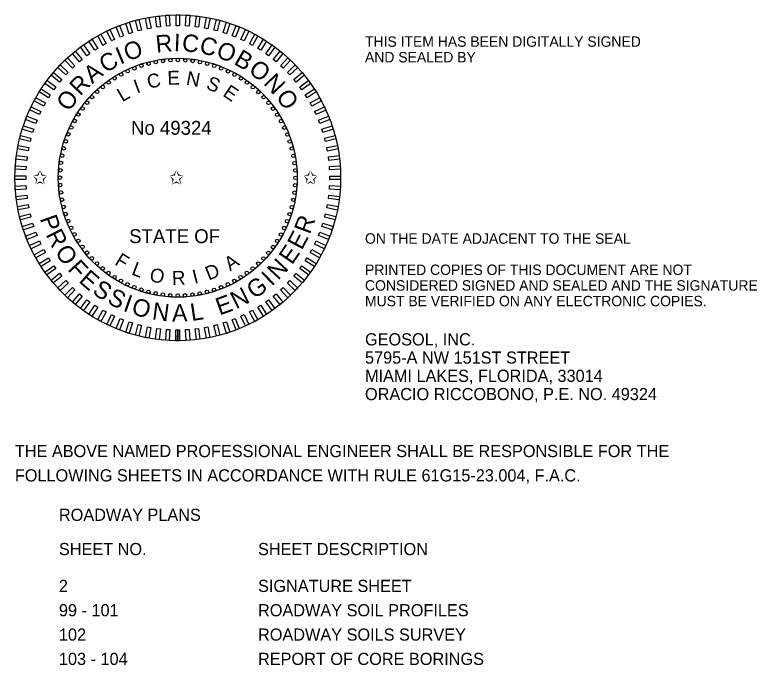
# Model space of a CAD drawing. Extents: x -811 to 10319, y -2309 to 9962.
# Drawn here: x -794.327 to -790.055, y -2192.952 to -2189.209 of the extents above; entities that cross this region are included whole.
import ezdxf

# ---------------------------------------------------------------- set-up
doc = ezdxf.new("R2010")
doc.units = 0
for name, color, linetype in [('PlotBorder_dp', 7, 'Continuous'), ('TextMinor', 7, 'Continuous'), ('TextMisc', 7, 'Continuous'), ('TextShtNo', 7, 'Continuous')]:
    doc.layers.add(name, color=color, linetype=linetype)

msp = doc.modelspace()

# ---------------------------------------------------------------- linework, layer by layer
at = {"layer": 'TextMinor'}
for radius in [0.9375, 0.6875]:
    msp.add_circle((-793.3899, -2190.1468), radius, dxfattribs=at)
at = {"layer": 'TextShtNo'}
for p, q in [((-793.3999, -2191.0843), (-793.4001, -2191.0218)), ((-793.3899, -2191.0843), (-793.3901, -2191.0218)), ((-793.3799, -2191.0843), (-793.3801, -2191.0218))]:
    msp.add_line(p, q, dxfattribs=at)
for points in [[(-793.5976, -2189.2967), (-793.6172, -2189.3018), (-793.6327, -2189.2413), (-793.6132, -2189.2363)], [(-793.5438, -2189.2854), (-793.5637, -2189.2892), (-793.5754, -2189.2278), (-793.5555, -2189.224)], [(-793.4895, -2189.2774), (-793.5095, -2189.2799), (-793.5173, -2189.218), (-793.4973, -2189.2155)], [(-793.4347, -2189.2729), (-793.4548, -2189.2741), (-793.4587, -2189.2118), (-793.4386, -2189.2106)], [(-793.3797, -2189.2718), (-793.3999, -2189.2718), (-793.3999, -2189.2093), (-793.3797, -2189.2093)], [(-793.3248, -2189.2741), (-793.3449, -2189.2729), (-793.341, -2189.2106), (-793.3209, -2189.2118)], [(-793.2701, -2189.28), (-793.2901, -2189.2774), (-793.2823, -2189.2155), (-793.2623, -2189.218)], [(-793.2159, -2189.2892), (-793.2357, -2189.2854), (-793.224, -2189.2241), (-793.2042, -2189.2279)], [(-793.1624, -2189.3018), (-793.182, -2189.2968), (-793.1664, -2189.2363), (-793.1469, -2189.2413)], [(-793.7025, -2189.3295), (-793.7213, -2189.3369), (-793.7443, -2189.2789), (-793.7255, -2189.2714)], [(-793.6506, -2189.3115), (-793.6698, -2189.3177), (-793.6891, -2189.2583), (-793.6699, -2189.2521)], [(-793.1098, -2189.3178), (-793.129, -2189.3115), (-793.1097, -2189.2521), (-793.0905, -2189.2584)], [(-793.0583, -2189.337), (-793.0771, -2189.3295), (-793.0541, -2189.2715), (-793.0353, -2189.2789)], [(-793.8025, -2189.3751), (-793.8202, -2189.3848), (-793.8503, -2189.3301), (-793.8326, -2189.3204)], [(-793.7532, -2189.3507), (-793.7715, -2189.3593), (-793.7981, -2189.3028), (-793.7798, -2189.2942)], [(-793.0081, -2189.3594), (-793.0264, -2189.3508), (-792.9998, -2189.2943), (-792.9815, -2189.3029)], [(-792.9594, -2189.3849), (-792.9771, -2189.3752), (-792.947, -2189.3205), (-792.9293, -2189.3302)], [(-793.8502, -2189.4025), (-793.8672, -2189.4134), (-793.9007, -2189.3606), (-793.8836, -2189.3498)], [(-792.9124, -2189.4135), (-792.9295, -2189.4026), (-792.896, -2189.3499), (-792.879, -2189.3607)], [(-793.896, -2189.4329), (-793.9123, -2189.4448), (-793.949, -2189.3943), (-793.9327, -2189.3824)], [(-792.8673, -2189.4449), (-792.8836, -2189.433), (-792.8469, -2189.3825), (-792.8306, -2189.3944)], [(-793.9815, -2189.502), (-793.9962, -2189.5158), (-794.0389, -2189.4703), (-794.0242, -2189.4565)], [(-793.9398, -2189.4661), (-793.9554, -2189.479), (-793.9952, -2189.4309), (-793.9796, -2189.418)], [(-792.8243, -2189.4791), (-792.8398, -2189.4662), (-792.8, -2189.4181), (-792.7845, -2189.431)], [(-792.7835, -2189.5159), (-792.7982, -2189.5021), (-792.7554, -2189.4566), (-792.7407, -2189.4704)], [(-794.0208, -2189.5404), (-794.0346, -2189.5551), (-794.0801, -2189.5124), (-794.0663, -2189.4976)], [(-792.745, -2189.5552), (-792.7589, -2189.5405), (-792.7133, -2189.4978), (-792.6995, -2189.5125)], [(-794.0576, -2189.5812), (-794.0705, -2189.5968), (-794.1186, -2189.5569), (-794.1057, -2189.5414)], [(-792.7092, -2189.5969), (-792.722, -2189.5813), (-792.6739, -2189.5415), (-792.6611, -2189.5571)], [(-794.0918, -2189.6242), (-794.1037, -2189.6406), (-794.1542, -2189.6039), (-794.1423, -2189.5875)], [(-792.676, -2189.6407), (-792.6878, -2189.6244), (-792.6373, -2189.5877), (-792.6255, -2189.604)], [(-794.1232, -2189.6693), (-794.1341, -2189.6864), (-794.1868, -2189.6529), (-794.176, -2189.6359)], [(-792.6456, -2189.6865), (-792.6564, -2189.6695), (-792.6037, -2189.636), (-792.5929, -2189.6531)], [(-794.1518, -2189.7163), (-794.1615, -2189.734), (-794.2162, -2189.7039), (-794.2065, -2189.6863)], [(-792.6182, -2189.7342), (-792.6279, -2189.7165), (-792.5732, -2189.6864), (-792.5635, -2189.7041)], [(-794.1773, -2189.765), (-794.1859, -2189.7833), (-794.2424, -2189.7567), (-794.2338, -2189.7384)], [(-792.5938, -2189.7835), (-792.6024, -2189.7652), (-792.5459, -2189.7386), (-792.5373, -2189.7569)], [(-794.1997, -2189.8152), (-794.2071, -2189.834), (-794.2652, -2189.811), (-794.2578, -2189.7922)], [(-792.5726, -2189.8342), (-792.58, -2189.8154), (-792.5219, -2189.7924), (-792.5145, -2189.8112)], [(-794.2189, -2189.8667), (-794.2252, -2189.8859), (-794.2846, -2189.8666), (-794.2783, -2189.8474)], [(-792.5545, -2189.8861), (-792.5608, -2189.8669), (-792.5014, -2189.8476), (-792.4952, -2189.8668)], [(-794.2349, -2189.9193), (-794.2399, -2189.9389), (-794.3004, -2189.9234), (-794.2954, -2189.9038)], [(-792.5398, -2189.9391), (-792.5448, -2189.9195), (-792.4844, -2189.904), (-792.4793, -2189.9235)], [(-794.2475, -2189.9728), (-794.2513, -2189.9927), (-794.3126, -2189.981), (-794.3088, -2189.9611)], [(-792.5284, -2189.9929), (-792.5322, -2189.973), (-792.4709, -2189.9613), (-792.4671, -2189.9812)], [(-794.2567, -2190.027), (-794.2593, -2190.0471), (-794.3212, -2190.0392), (-794.3187, -2190.0192)], [(-792.5205, -2190.0472), (-792.523, -2190.0272), (-792.4611, -2190.0194), (-792.4585, -2190.0394)], [(-794.2626, -2190.0817), (-794.2638, -2190.1018), (-794.3261, -2190.0979), (-794.3249, -2190.0778)], [(-792.5159, -2190.102), (-792.5172, -2190.0819), (-792.4549, -2190.078), (-792.4536, -2190.0981)], [(-794.2649, -2190.1366), (-794.2649, -2190.1568), (-794.3274, -2190.1568), (-794.3274, -2190.1366)], [(-792.5149, -2190.157), (-792.5149, -2190.1368), (-792.4524, -2190.1368), (-792.4524, -2190.157)], [(-794.2638, -2190.1916), (-794.2626, -2190.2117), (-794.3249, -2190.2157), (-794.3261, -2190.1955)], [(-792.5172, -2190.2119), (-792.516, -2190.1918), (-792.4536, -2190.1957), (-792.4549, -2190.2158)], [(-794.2593, -2190.2464), (-794.2568, -2190.2664), (-794.3187, -2190.2742), (-794.3212, -2190.2542)], [(-792.523, -2190.2666), (-792.5205, -2190.2466), (-792.4586, -2190.2544), (-792.4611, -2190.2744)], [(-794.2513, -2190.3008), (-794.2475, -2190.3206), (-794.3089, -2190.3323), (-794.3127, -2190.3125)], [(-792.5323, -2190.3208), (-792.5285, -2190.301), (-792.4671, -2190.3127), (-792.4709, -2190.3325)], [(-794.24, -2190.3546), (-794.2349, -2190.3741), (-794.2954, -2190.3896), (-794.3004, -2190.3701)], [(-792.5449, -2190.3743), (-792.5399, -2190.3547), (-792.4794, -2190.3703), (-792.4844, -2190.3898)], [(-794.2252, -2190.4075), (-794.219, -2190.4267), (-794.2784, -2190.446), (-794.2846, -2190.4268)], [(-792.5608, -2190.4269), (-792.5546, -2190.4077), (-792.4952, -2190.427), (-792.5014, -2190.4462)], [(-794.2072, -2190.4595), (-794.1998, -2190.4782), (-794.2578, -2190.5012), (-794.2653, -2190.4824)], [(-792.5801, -2190.4784), (-792.5726, -2190.4596), (-792.5146, -2190.4826), (-792.522, -2190.5014)], [(-794.186, -2190.5102), (-794.1774, -2190.5284), (-794.2339, -2190.555), (-794.2425, -2190.5367)], [(-792.6025, -2190.5286), (-792.5939, -2190.5103), (-792.5374, -2190.5369), (-792.546, -2190.5552)], [(-794.1616, -2190.5594), (-794.1519, -2190.5771), (-794.2066, -2190.6072), (-794.2163, -2190.5895)], [(-792.628, -2190.5773), (-792.6183, -2190.5596), (-792.5636, -2190.5897), (-792.5733, -2190.6074)], [(-794.1342, -2190.6071), (-794.1233, -2190.6241), (-794.1761, -2190.6576), (-794.1869, -2190.6405)], [(-792.6565, -2190.6243), (-792.6457, -2190.6072), (-792.593, -2190.6407), (-792.6038, -2190.6577)], [(-794.1038, -2190.6529), (-794.0919, -2190.6692), (-794.1424, -2190.7059), (-794.1543, -2190.6896)], [(-792.688, -2190.6694), (-792.6761, -2190.653), (-792.6256, -2190.6898), (-792.6374, -2190.7061)], [(-794.0706, -2190.6967), (-794.0577, -2190.7123), (-794.1058, -2190.7521), (-794.1187, -2190.7365)], [(-794.0347, -2190.7384), (-794.0209, -2190.7531), (-794.0664, -2190.7958), (-794.0802, -2190.7811)], [(-792.759, -2190.7532), (-792.7452, -2190.7385), (-792.6997, -2190.7813), (-792.7135, -2190.796)], [(-792.7222, -2190.7124), (-792.7093, -2190.6969), (-792.6612, -2190.7367), (-792.674, -2190.7522)], [(-793.9963, -2190.7777), (-793.9816, -2190.7915), (-794.0243, -2190.837), (-794.0391, -2190.8232)], [(-792.7983, -2190.7917), (-792.7836, -2190.7778), (-792.7409, -2190.8234), (-792.7556, -2190.8372)], [(-793.9555, -2190.8145), (-793.9399, -2190.8274), (-793.9797, -2190.8755), (-793.9953, -2190.8627)], [(-792.84, -2190.8275), (-792.8244, -2190.8147), (-792.7846, -2190.8628), (-792.8002, -2190.8756)], [(-793.9125, -2190.8487), (-793.8961, -2190.8606), (-793.9328, -2190.9111), (-793.9492, -2190.8993)], [(-792.8838, -2190.8607), (-792.8675, -2190.8488), (-792.8308, -2190.8994), (-792.8471, -2190.9112)], [(-793.8674, -2190.8802), (-793.8503, -2190.891), (-793.8838, -2190.9437), (-793.9008, -2190.9329)], [(-793.8204, -2190.9087), (-793.8027, -2190.9184), (-793.8328, -2190.9731), (-793.8504, -2190.9634)], [(-792.9773, -2190.9185), (-792.9596, -2190.9088), (-792.9295, -2190.9635), (-792.9472, -2190.9732)], [(-792.9296, -2190.8911), (-792.9126, -2190.8803), (-792.8791, -2190.933), (-792.8962, -2190.9438)], [(-793.7717, -2190.9342), (-793.7534, -2190.9428), (-793.78, -2190.9993), (-793.7983, -2190.9907)], [(-793.0265, -2190.9429), (-793.0083, -2190.9343), (-792.9817, -2190.9908), (-792.9999, -2190.9994)], [(-793.7215, -2190.9566), (-793.7027, -2190.9641), (-793.7257, -2191.0221), (-793.7445, -2191.0147)], [(-793.67, -2190.9759), (-793.6508, -2190.9821), (-793.6701, -2191.0415), (-793.6893, -2191.0352)], [(-793.6174, -2190.9918), (-793.5978, -2190.9968), (-793.6133, -2191.0573), (-793.6329, -2191.0523)], [(-793.1821, -2190.9969), (-793.1626, -2190.9919), (-793.1471, -2191.0523), (-793.1666, -2191.0574)], [(-793.1292, -2190.9822), (-793.11, -2190.9759), (-793.0907, -2191.0353), (-793.1099, -2191.0415)], [(-793.0772, -2190.9641), (-793.0585, -2190.9567), (-793.0355, -2191.0148), (-793.0543, -2191.0222)], [(-793.5639, -2191.0044), (-793.544, -2191.0082), (-793.5557, -2191.0695), (-793.5756, -2191.0658)], [(-793.5097, -2191.0137), (-793.4896, -2191.0162), (-793.4975, -2191.0781), (-793.5175, -2191.0756)], [(-793.455, -2191.0195), (-793.4348, -2191.0207), (-793.4388, -2191.0831), (-793.4589, -2191.0818)], [(-793.4001, -2191.0218), (-793.3799, -2191.0218), (-793.3799, -2191.0843), (-793.4001, -2191.0843)], [(-793.3451, -2191.0208), (-793.325, -2191.0195), (-793.321, -2191.0818), (-793.3412, -2191.0831)], [(-793.2903, -2191.0162), (-793.2703, -2191.0137), (-793.2625, -2191.0756), (-793.2825, -2191.0782)], [(-793.2359, -2191.0082), (-793.2161, -2191.0045), (-793.2044, -2191.0658), (-793.2242, -2191.0696)]]:
    msp.add_lwpolyline(points, close=True, dxfattribs=at)
for centre in [(-793.5987, -2189.5023), (-793.5578, -2189.4905), (-793.5163, -2189.4812), (-793.4742, -2189.4746), (-793.4319, -2189.4706), (-793.3893, -2189.4693), (-793.3468, -2189.4707), (-793.3044, -2189.4748), (-793.2624, -2189.4814), (-793.2209, -2189.4908), (-793.18, -2189.5027), (-793.7158, -2189.5529), (-793.6778, -2189.5336), (-793.6388, -2189.5167), (-793.14, -2189.5171), (-793.1009, -2189.5341), (-793.7524, -2189.5745), (-793.063, -2189.5534), (-793.0264, -2189.5751), (-793.8213, -2189.6245), (-793.7876, -2189.5984), (-792.9912, -2189.5991), (-792.9576, -2189.6252), (-793.8532, -2189.6526), (-792.9257, -2189.6533), (-793.9115, -2189.7145), (-793.8834, -2189.6826), (-792.8956, -2189.6835), (-792.8675, -2189.7154), (-793.9376, -2189.7481), (-792.8415, -2189.7491), (-793.9616, -2189.7833), (-792.8176, -2189.7843), (-793.9833, -2189.8199), (-792.7959, -2189.8209), (-794.0026, -2189.8578), (-792.7767, -2189.8589), (-794.034, -2189.9369), (-794.0196, -2189.8969), (-792.7598, -2189.8979), (-794.0459, -2189.9778), (-792.7454, -2189.938), (-792.7336, -2189.9789), (-794.0552, -2190.0193), (-792.7243, -2190.0204), (-794.0619, -2190.0613), (-792.7177, -2190.0625), (-794.066, -2190.1037), (-792.7137, -2190.1048), (-794.0674, -2190.1462), (-792.7124, -2190.1474), (-794.0661, -2190.1888), (-792.7138, -2190.1899), (-794.0621, -2190.2312), (-792.7178, -2190.2323), (-794.0555, -2190.2732), (-792.7245, -2190.2743), (-794.0462, -2190.3147), (-792.7338, -2190.3158), (-794.0344, -2190.3556), (-792.7457, -2190.3567), (-794.02, -2190.3957), (-792.7602, -2190.3967), (-794.0031, -2190.4348), (-792.7771, -2190.4358), (-793.9838, -2190.4727), (-792.7965, -2190.4737), (-793.9622, -2190.5093), (-792.8182, -2190.5103), (-793.9383, -2190.5446), (-793.9122, -2190.5782), (-792.8421, -2190.5455), (-793.8841, -2190.6102), (-792.8964, -2190.611), (-792.8682, -2190.5791), (-793.8541, -2190.6403), (-792.9265, -2190.641), (-793.8222, -2190.6684), (-793.7885, -2190.6946), (-792.9921, -2190.6952), (-792.9585, -2190.6692), (-793.7534, -2190.7185), (-793.7168, -2190.7402), (-793.064, -2190.7408), (-793.0274, -2190.7191), (-793.6788, -2190.7596), (-793.6398, -2190.7765), (-793.5998, -2190.7909), (-793.1811, -2190.7913), (-793.141, -2190.7769), (-793.1019, -2190.76), (-793.5589, -2190.8029), (-793.5174, -2190.8122), (-793.4754, -2190.8189), (-793.433, -2190.8229), (-793.3899, -2190.8243), (-793.3479, -2190.823), (-793.3055, -2190.819), (-793.2635, -2190.8124), (-793.222, -2190.8031)]:
    msp.add_circle(centre, 0.01, dxfattribs=at)

# ---------------------------------------------------------------- texts
at = {"layer": 'PlotBorder_dp'}
for s, height, p in [('THIS ITEM HAS BEEN DIGITALLY SIGNED ', 0.06, (-792.3122, -2189.393)), ('AND SEALED BY', 0.06, (-792.3122, -2189.483)), ('ON THE DATE ADJACENT TO THE SEAL', 0.06, (-792.3122, -2190.5264)), ('PRINTED COPIES OF THIS DOCUMENT ARE NOT ', 0.06, (-792.3122, -2190.7064)), ('CONSIDERED SIGNED AND SEALED AND THE SIGNATURE ', 0.06, (-792.3122, -2190.7964)), ('MUST BE VERIFIED ON ANY ELECTRONIC COPIES.', 0.06, (-792.3122, -2190.8864)), ('GEOSOL, INC.', 0.07, (-792.3122, -2191.1116)), ('5795-A NW 151ST STREET', 0.07, (-792.3122, -2191.2166)), ('MIAMI LAKES, FLORIDA, 33014', 0.07, (-792.3122, -2191.3216)), ('ORACIO RICCOBONO, P.E. NO. 49324', 0.07, (-792.3122, -2191.4266)), ('THE ABOVE NAMED PROFESSIONAL ENGINEER SHALL BE RESPONSIBLE FOR THE ', 0.07, (-794.3274, -2191.7544)), ('FOLLOWING SHEETS IN ACCORDANCE WITH RULE 61G15-23.004, F.A.C.', 0.07, (-794.3274, -2191.8944)), ('ROADWAY PLANS', 0.07, (-794.0737, -2192.1214))]:
    msp.add_text(s, height=height, dxfattribs=at).set_placement(p)
at = {"layer": 'TextMisc'}
for s, p in [('SHEET NO.', (-794.0737, -2192.3184)), ('SHEET DESCRIPTION', (-792.9278, -2192.3184)), ('2', (-794.0737, -2192.5306)), ('SIGNATURE SHEET', (-792.9278, -2192.5306)), ('99 - 101', (-794.0737, -2192.6706)), ('ROADWAY SOIL PROFILES', (-792.9278, -2192.6706)), ('102', (-794.0737, -2192.8106)), ('ROADWAY SOILS SURVEY', (-792.9278, -2192.8106)), ('103 - 104', (-794.0737, -2192.9506)), ('REPORT OF CORE BORINGS', (-792.9278, -2192.9506))]:
    msp.add_text(s, height=0.07, dxfattribs=at).set_placement(p)
at = {"layer": 'TextShtNo'}
for s, height, rotation, p in [('R', 0.1, 5.3723, (-793.5127, -2189.4277)), ('I', 0.1, 357.5509, (-793.4137, -2189.4176)), ('C', 0.1, 354.0177, (-793.3688, -2189.4175)), ('O', 0.1, 19.1125, (-793.68, -2189.4774)), ('C', 0.1, 346.2809, (-793.2708, -2189.427)), ('O', 0.1, 338.5441, (-793.175, -2189.4496)), ('I', 0.1, 22.6457, (-793.7207, -2189.4966)), ('B', 0.1, 329.8833, (-793.0724, -2189.4899)), ('C', 0.1, 30.3825, (-793.8053, -2189.547)), ('A', 0.1, 38.1495, (-793.8825, -2189.6087)), ('O', 0.1, 322.2793, (-792.9883, -2189.5377)), ('E', 0.08, 0.4186, (-793.4496, -2189.6117)), ('N', 0.08, 349.2914, (-793.3452, -2189.6103)), ('R', 0.1, 45.9708, (-793.9512, -2189.6807)), ('I', 0.08, 20.0117, (-793.6256, -2189.6627)), ('C', 0.08, 12.2025, (-793.5576, -2189.6352)), ('S', 0.08, 337.0221, (-793.2322, -2189.632)), ('N', 0.1, 313.6185, (-792.9011, -2189.6051)), ('E', 0.08, 325.8663, (-793.1356, -2189.6722)), ('O', 0.1, 54.6317, (-794.015, -2189.7705)), ('L', 0.08, 30.4021, (-793.709, -2189.7132)), ('O', 0.1, 305.3683, (-792.8285, -2189.6809)), ('P', 0.1, 289.4055, (-794.1846, -2190.3814)), ('R', 0.1, 69.5134, (-792.6297, -2190.4765)), ('R', 0.1, 296.1458, (-794.1516, -2190.473)), ('E', 0.1, 62.4712, (-792.6759, -2190.5672)), ('O', 0.1, 303.9671, (-794.1001, -2190.5737)), ('E', 0.1, 55.4289, (-792.7328, -2190.6516)), ('F', 0.08, 328.7241, (-793.7579, -2190.6434)), ('A', 0.08, 34.4992, (-793.088, -2190.6862)), ('N', 0.1, 47.1788, (-792.812, -2190.7407)), ('F', 0.1, 312.628, (-794.0277, -2190.6757)), ('L', 0.08, 339.2916, (-793.6606, -2190.7025)), ('D', 0.08, 22.0128, (-793.2118, -2190.7387)), ('E', 0.1, 319.0783, (-793.9643, -2190.744)), ('O', 0.08, 349.6821, (-793.556, -2190.7422)), ('R', 0.08, 2.3398, (-793.4215, -2190.7641)), ('I', 0.08, 14.2037, (-793.2939, -2190.7574)), ('I', 0.1, 43.6456, (-792.8497, -2190.7751)), ('G', 0.1, 35.1115, (-792.9489, -2190.8483)), ('S', 0.1, 326.1206, (-793.8867, -2190.81)), ('N', 0.1, 26.8614, (-793.0542, -2190.9044)), ('S', 0.1, 333.193, (-793.8013, -2190.8661)), ('I', 0.1, 340.2654, (-793.7096, -2190.9113)), ('E', 0.1, 19.8191, (-793.1496, -2190.9398)), ('O', 0.1, 343.7986, (-793.6619, -2190.9295)), ('N', 0.1, 352.4595, (-793.5409, -2190.9615)), ('A', 0.1, 0.7097, (-793.4224, -2190.9748)), ('L', 0.1, 8.4767, (-793.3102, -2190.9716))]:
    msp.add_text(s, height=height, rotation=rotation, dxfattribs=at).set_placement(p)
for s, p in [('No 49324', (-793.6588, -2189.8996)), ('✩', (-794.2249, -2190.1848)), ('✩', (-793.4401, -2190.1848)), ('✩', (-792.6683, -2190.1848)), ('STATE OF', (-793.6696, -2190.523))]:
    msp.add_text(s, height=0.08, dxfattribs=at).set_placement(p)

doc.saveas('drawing.dxf')
